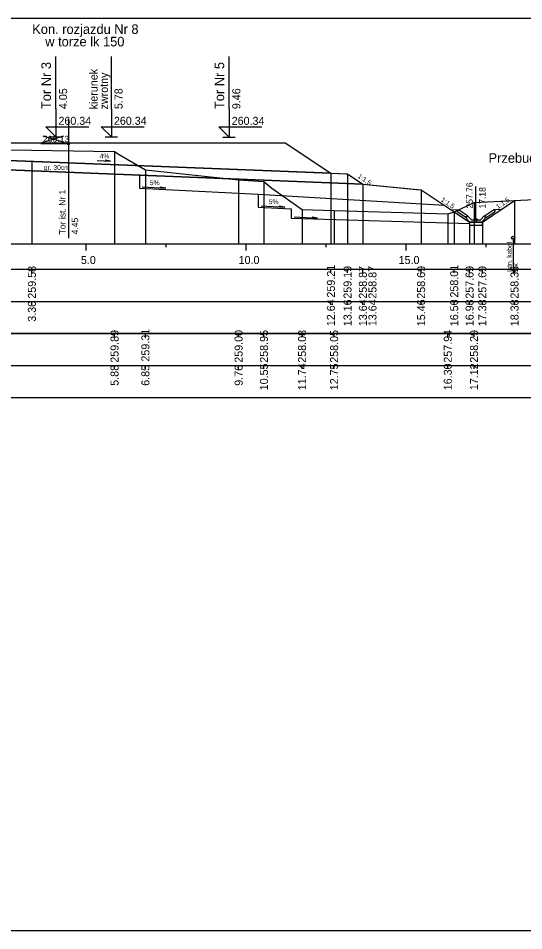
# Model space of a CAD drawing. Extents: x 6516023 to 6560129, y 5513077 to 5529206.
# Drawn here: x 6516681.09 to 6516696.88, y 5514451.16 to 5514479.66 of the extents above; entities that cross this region are included whole.
import ezdxf

# ---------------------------------------------------------------- set-up
doc = ezdxf.new("R2010")
doc.units = 0
for name, color, linetype in [('IR_default', 7, 'Continuous'), ('TOR_PRZEK_P-inne branze', 7, 'Continuous'), ('TOR_PRZEK_P-kable', 7, 'Continuous'), ('TOR_PRZEK_P-komponent', 7, 'Continuous'), ('TOR_PRZEK_P-odwodnienie', 7, 'Continuous'), ('TOR_PRZEK_P-opisy', 7, 'Continuous'), ('TOR_PRZEK_P-schodkowanie+wymiana', 7, 'Continuous'), ('TOR_PRZEK_P-tabelka istniejace', 7, 'Continuous'), ('TOR_PRZEK_P-tabelka projektowane', 7, 'Continuous'), ('TOR_PRZEK_P-teren istniejacy', 7, 'Continuous'), ('TOR_PRZEK_P-tory istniejace', 7, 'Continuous'), ('TOR_PRZEK_P-tory projektowane', 7, 'Continuous'), ('TOR_PRZEK_P-uklad odniesienia', 7, 'Continuous'), ('TOR_PRZEK_P-warstwa ochronna I', 7, 'Continuous'), ('TOR_PRZEK_P-warstwa ochronna II', 7, 'Continuous'), ('TOR_PS_T-skarpy projektowane', 7, 'Continuous'), ('TOR_RAMKI-ramka+tabelka 1', 7, 'Continuous')]:
    doc.layers.add(name, color=color, linetype=linetype)

msp = doc.modelspace()

# ---------------------------------------------------------------- linework, layer by layer
at = {"layer": 'IR_default'}
msp.add_lwpolyline([(6516680.667, 5514475.768), (6516682.263, 5514475.768), (6516682.417, 5514475.768), (6516684.013, 5514475.768), (6516685.751, 5514475.767), (6516685.927, 5514475.767), (6516689.119, 5514475.767), (6516689.427, 5514475.767), (6516690.731, 5514474.898), (6516690.857, 5514474.814), (6516691.332, 5514474.795), (6516691.377, 5514474.793), (6516691.856, 5514474.474), (6516691.856, 5514474.474), (6516693.531, 5514474.307), (6516693.677, 5514474.301), (6516694.62, 5514473.672), (6516694.71, 5514473.612), (6516695.148, 5514473.32), (6516695.19, 5514473.292), (6516695.555, 5514473.292), (6516695.59, 5514473.292), (6516696.274, 5514473.748), (6516696.595, 5514473.962)], dxfattribs=at)
at = {"layer": 'TOR_PRZEK_P-kable'}
msp.add_line((6516696.554, 5514472.803), (6516696.554, 5514471.693), dxfattribs=at)
msp.add_circle((6516696.554, 5514472.803), 0.05, dxfattribs=at)
at = {"layer": 'TOR_PRZEK_P-komponent'}
for points in [[(6516671.963, 5514475.767), (6516673.713, 5514475.767), (6516672.659, 5514475.767), (6516675.463, 5514475.767), (6516676.463, 5514475.767), (6516678.213, 5514475.767), (6516679.963, 5514475.767), (6516680.513, 5514475.768), (6516682.263, 5514475.768), (6516684.013, 5514475.768), (6516685.927, 5514475.767), (6516689.427, 5514475.767), (6516690.857, 5514474.814), (6516680.238, 5514475.238), (6516670.591, 5514474.852)], [(6516670.013, 5514474.829), (6516680.238, 5514475.238), (6516691.377, 5514474.793), (6516691.856, 5514474.474), (6516680.238, 5514474.938), (6516669.534, 5514474.51)]]:
    msp.add_lwpolyline(points, close=True, dxfattribs=at)
at = {"layer": 'TOR_PRZEK_P-odwodnienie'}
for p, q in [((6516695.39, 5514473.362), (6516695.39, 5514474.406)), ((6516695.081, 5514473.421), (6516694.82, 5514473.595)), ((6516695.126, 5514473.487), (6516694.845, 5514473.674)), ((6516695.655, 5514473.487), (6516695.935, 5514473.674)), ((6516695.699, 5514473.421), (6516695.961, 5514473.595)), ((6516695.093, 5514473.437), (6516695.081, 5514473.421)), ((6516695.083, 5514473.457), (6516695.13, 5514473.481)), ((6516695.126, 5514473.487), (6516695.117, 5514473.475)), ((6516695.25, 5514473.362), (6516695.13, 5514473.481)), ((6516695.2, 5514473.292), (6516695.58, 5514473.292)), ((6516695.25, 5514473.362), (6516695.53, 5514473.362)), ((6516695.53, 5514473.362), (6516695.65, 5514473.481)), ((6516695.65, 5514473.481), (6516695.698, 5514473.457)), ((6516695.655, 5514473.487), (6516695.663, 5514473.475)), ((6516695.688, 5514473.437), (6516695.699, 5514473.421))]:
    msp.add_line(p, q, dxfattribs=at)
for points in [[(6516694.599, 5514473.686), (6516694.845, 5514473.674)], [(6516694.795, 5514473.648), (6516694.845, 5514473.674)], [(6516694.795, 5514473.648), (6516694.82, 5514473.595)], [(6516696.182, 5514473.686), (6516695.935, 5514473.674)], [(6516695.986, 5514473.648), (6516695.935, 5514473.674)], [(6516695.986, 5514473.648), (6516695.961, 5514473.595)], [(6516695.117, 5514473.475), (6516695.082, 5514473.456)], [(6516695.082, 5514473.456), (6516695.093, 5514473.437)], [(6516695.13, 5514473.362), (6516695.083, 5514473.457)], [(6516695.2, 5514473.292), (6516695.13, 5514473.362)], [(6516695.19, 5514473.292), (6516695.19, 5514473.292), (6516695.19, 5514473.292), (6516695.19, 5514473.291), (6516695.19, 5514473.292), (6516695.191, 5514473.291), (6516695.19, 5514473.292), (6516695.191, 5514473.292)], [(6516695.59, 5514473.292), (6516695.19, 5514473.292), (6516695.19, 5514473.192), (6516695.59, 5514473.192), (6516695.59, 5514473.292)], [(6516695.58, 5514473.292), (6516695.65, 5514473.362)], [(6516695.59, 5514473.292), (6516695.59, 5514473.292), (6516695.59, 5514473.292), (6516695.59, 5514473.291), (6516695.59, 5514473.292), (6516695.591, 5514473.291), (6516695.59, 5514473.292), (6516695.591, 5514473.292)], [(6516695.65, 5514473.362), (6516695.698, 5514473.457)], [(6516695.663, 5514473.475), (6516695.699, 5514473.456)], [(6516695.699, 5514473.456), (6516695.688, 5514473.437)]]:
    msp.add_lwpolyline(points, dxfattribs=at)
msp.add_circle((6516695.39, 5514473.362), 0.035, dxfattribs=at)
at = {"layer": 'TOR_PRZEK_P-opisy'}
msp.add_lwpolyline([(6516683.552, 5514475.211), (6516683.97, 5514475.192), (6516683.802, 5514475.22)], dxfattribs=at)
at = {"layer": 'TOR_PRZEK_P-schodkowanie+wymiana'}
for p, q in [((6516684.871, 5514474.753), (6516684.871, 5514474.347)), ((6516684.871, 5514474.347), (6516688.588, 5514474.161)), ((6516688.588, 5514474.161), (6516688.588, 5514473.755)), ((6516688.588, 5514474.161), (6516694.403, 5514473.816)), ((6516688.588, 5514473.755), (6516689.611, 5514473.704)), ((6516689.611, 5514473.704), (6516689.611, 5514473.412)), ((6516689.611, 5514473.412), (6516695.19, 5514473.242))]:
    msp.add_line(p, q, dxfattribs=at)
at = {"layer": 'TOR_PRZEK_P-tabelka istniejace'}
for p, q in [((6516684.096, 5514469.706), (6516684.096, 5514469.806)), ((6516685.06, 5514469.706), (6516685.06, 5514469.806)), ((6516687.973, 5514469.706), (6516687.973, 5514469.806)), ((6516688.765, 5514469.706), (6516688.765, 5514469.806)), ((6516689.956, 5514469.706), (6516689.956, 5514469.806)), ((6516690.958, 5514469.706), (6516690.958, 5514469.806)), ((6516694.509, 5514469.706), (6516694.509, 5514469.806)), ((6516695.33, 5514469.706), (6516695.33, 5514469.806)), ((6516637.163, 5514468.806), (6516720.963, 5514468.806)), ((6516684.096, 5514468.706), (6516684.096, 5514468.806)), ((6516685.06, 5514468.706), (6516685.06, 5514468.806)), ((6516687.973, 5514468.706), (6516687.973, 5514468.806)), ((6516688.765, 5514468.706), (6516688.765, 5514468.806)), ((6516689.956, 5514468.706), (6516689.956, 5514468.806)), ((6516690.958, 5514468.706), (6516690.958, 5514468.806)), ((6516694.509, 5514468.706), (6516694.509, 5514468.806)), ((6516695.33, 5514468.706), (6516695.33, 5514468.806))]:
    msp.add_line(p, q, dxfattribs=at)
for points in [[(6516684.096, 5514475.498), (6516684.096, 5514472.806), (6516684.096, 5514472.676), (6516684.096, 5514472.606)], [(6516685.06, 5514474.92), (6516685.06, 5514472.806), (6516685.06, 5514472.676), (6516685.06, 5514472.606)], [(6516687.973, 5514474.606), (6516687.973, 5514472.806), (6516687.973, 5514472.676), (6516687.973, 5514472.606)], [(6516688.765, 5514474.561), (6516688.765, 5514472.806), (6516688.765, 5514472.676), (6516688.765, 5514472.606)], [(6516695.33, 5514473.898), (6516695.33, 5514472.806), (6516695.33, 5514472.676), (6516695.33, 5514472.606)], [(6516689.956, 5514473.684), (6516689.956, 5514472.806), (6516689.956, 5514472.676), (6516689.956, 5514472.606)], [(6516690.958, 5514473.653), (6516690.958, 5514472.806), (6516690.958, 5514472.676), (6516690.958, 5514472.606)], [(6516694.509, 5514473.548), (6516694.509, 5514472.806), (6516694.509, 5514472.676), (6516694.509, 5514472.606)]]:
    msp.add_lwpolyline(points, dxfattribs=at)
msp.add_lwpolyline([(6516637.163, 5514469.806), (6516637.163, 5514467.806), (6516720.963, 5514467.806), (6516720.963, 5514469.806)], close=True, dxfattribs=at)
at = {"layer": 'TOR_PRZEK_P-tabelka projektowane'}
for p, q in [((6516681.513, 5514471.706), (6516681.513, 5514471.806)), ((6516690.857, 5514471.706), (6516690.857, 5514471.806)), ((6516691.377, 5514471.706), (6516691.377, 5514471.806)), ((6516691.856, 5514471.706), (6516691.856, 5514471.806)), ((6516693.677, 5514471.706), (6516693.677, 5514471.806)), ((6516694.71, 5514471.706), (6516694.71, 5514471.806)), ((6516695.19, 5514471.706), (6516695.19, 5514471.806)), ((6516695.59, 5514471.706), (6516695.59, 5514471.806)), ((6516696.595, 5514471.706), (6516696.595, 5514471.806)), ((6516637.163, 5514470.806), (6516720.963, 5514470.806)), ((6516681.513, 5514470.706), (6516681.513, 5514470.806)), ((6516690.857, 5514470.706), (6516690.857, 5514470.806)), ((6516691.377, 5514470.706), (6516691.377, 5514470.806)), ((6516691.856, 5514470.706), (6516691.856, 5514470.806)), ((6516693.677, 5514470.706), (6516693.677, 5514470.806)), ((6516694.71, 5514470.706), (6516694.71, 5514470.806)), ((6516695.19, 5514470.706), (6516695.19, 5514470.806)), ((6516695.59, 5514470.706), (6516695.59, 5514470.806)), ((6516696.595, 5514470.706), (6516696.595, 5514470.806))]:
    msp.add_line(p, q, dxfattribs=at)
for points in [[(6516681.513, 5514475.188), (6516681.513, 5514472.806), (6516681.513, 5514472.676), (6516681.513, 5514472.606)], [(6516690.857, 5514474.814), (6516690.857, 5514472.806), (6516690.857, 5514472.676), (6516690.857, 5514472.606)], [(6516691.377, 5514474.793), (6516691.377, 5514472.806), (6516691.377, 5514472.676), (6516691.377, 5514472.606)], [(6516691.856, 5514474.474), (6516691.856, 5514472.806), (6516691.856, 5514472.676), (6516691.856, 5514472.606)], [(6516693.677, 5514474.301), (6516693.677, 5514472.806), (6516693.677, 5514472.676), (6516693.677, 5514472.606)], [(6516696.595, 5514473.962), (6516696.595, 5514472.806), (6516696.595, 5514472.676), (6516696.595, 5514472.606)], [(6516694.71, 5514473.612), (6516694.71, 5514472.806), (6516694.71, 5514472.676), (6516694.71, 5514472.606)], [(6516695.19, 5514473.292), (6516695.19, 5514472.806), (6516695.19, 5514472.676), (6516695.19, 5514472.606)], [(6516695.59, 5514473.292), (6516695.59, 5514472.806), (6516695.59, 5514472.676), (6516695.59, 5514472.606)]]:
    msp.add_lwpolyline(points, dxfattribs=at)
msp.add_lwpolyline([(6516637.163, 5514471.806), (6516637.163, 5514469.806), (6516720.963, 5514469.806), (6516720.963, 5514471.806)], close=True, dxfattribs=at)
at = {"layer": 'TOR_PRZEK_P-teren istniejacy'}
msp.add_lwpolyline([(6516666.573, 5514475.104), (6516667.46, 5514475.506), (6516668.217, 5514475.533), (6516670.569, 5514475.616), (6516670.766, 5514475.522), (6516671.519, 5514475.169), (6516672.091, 5514475.169), (6516672.2, 5514475.171), (6516672.388, 5514475.284), (6516673.11, 5514475.685), (6516675.652, 5514475.631), (6516684.096, 5514475.498), (6516684.242, 5514475.398), (6516685.06, 5514474.92), (6516687.973, 5514474.606), (6516688.765, 5514474.561), (6516689.013, 5514474.344), (6516689.956, 5514473.684), (6516690.958, 5514473.653), (6516694.509, 5514473.548), (6516694.72, 5514473.61), (6516695.33, 5514473.898), (6516698.471, 5514474.057)], dxfattribs=at)
at = {"layer": 'TOR_PRZEK_P-tory istniejace'}
for p, q in [((6516682.658, 5514476.512), (6516682.658, 5514472.791)), ((6516681.858, 5514475.783), (6516682.51, 5514475.986)), ((6516681.858, 5514475.986), (6516682.51, 5514475.783)), ((6516682.658, 5514475.736), (6516681.792, 5514475.736))]:
    msp.add_line(p, q, dxfattribs=at)
msp.add_circle((6516682.658, 5514475.736), 0.035, dxfattribs=at)
at = {"layer": 'TOR_PRZEK_P-tory projektowane'}
for p, q in [((6516682.263, 5514476.826), (6516682.263, 5514478.458)), ((6516683.996, 5514476.826), (6516683.996, 5514478.458)), ((6516687.677, 5514476.825), (6516687.677, 5514478.457)), ((6516682.263, 5514476.826), (6516682.263, 5514475.948)), ((6516683.996, 5514476.826), (6516683.996, 5514475.948)), ((6516687.677, 5514476.825), (6516687.677, 5514475.947)), ((6516682.263, 5514475.948), (6516681.944, 5514476.267)), ((6516681.944, 5514476.267), (6516683.288, 5514476.267)), ((6516683.996, 5514475.948), (6516683.677, 5514476.267)), ((6516683.677, 5514476.267), (6516685.021, 5514476.267)), ((6516687.677, 5514475.947), (6516687.358, 5514476.266)), ((6516687.358, 5514476.266), (6516688.702, 5514476.266)), ((6516682.071, 5514475.948), (6516682.455, 5514475.948)), ((6516683.805, 5514475.948), (6516684.188, 5514475.948)), ((6516687.485, 5514475.947), (6516687.869, 5514475.947))]:
    msp.add_line(p, q, dxfattribs=at)
at = {"layer": 'TOR_PRZEK_P-uklad odniesienia'}
for p, q in [((6516640.963, 5514472.606), (6516720.963, 5514472.606)), ((6516683.213, 5514472.406), (6516683.213, 5514472.606)), ((6516685.713, 5514472.506), (6516685.713, 5514472.606)), ((6516688.213, 5514472.406), (6516688.213, 5514472.606)), ((6516690.713, 5514472.506), (6516690.713, 5514472.606)), ((6516693.213, 5514472.406), (6516693.213, 5514472.606)), ((6516695.713, 5514472.506), (6516695.713, 5514472.606))]:
    msp.add_line(p, q, dxfattribs=at)
at = {"layer": 'TOR_PRZEK_P-warstwa ochronna I'}
msp.add_lwpolyline([(6516669.534, 5514474.51), (6516680.238, 5514474.938), (6516691.856, 5514474.474)], dxfattribs=at)
at = {"layer": 'TOR_PRZEK_P-warstwa ochronna II'}
msp.add_lwpolyline([(6516659.779, 5514474.338), (6516660.886, 5514474.36), (6516662.236, 5514473.459), (6516662.636, 5514473.459), (6516663.041, 5514473.729), (6516663.713, 5514474.177), (6516669.534, 5514474.51), (6516670.013, 5514474.829), (6516670.591, 5514474.852), (6516678.963, 5514475.187), (6516680.238, 5514475.238), (6516681.513, 5514475.188), (6516690.857, 5514474.814), (6516691.377, 5514474.793), (6516691.856, 5514474.474), (6516693.677, 5514474.301), (6516694.71, 5514473.612), (6516695.19, 5514473.292), (6516695.59, 5514473.292), (6516696.595, 5514473.962)], dxfattribs=at)
at = {"layer": 'TOR_PS_T-skarpy projektowane'}
for points in [[(6516684.964, 5514474.391), (6516685.699, 5514474.352), (6516685.526, 5514474.382)], [(6516688.681, 5514473.799), (6516689.416, 5514473.76), (6516689.244, 5514473.791)], [(6516689.704, 5514473.457), (6516690.439, 5514473.417), (6516690.267, 5514473.448)]]:
    msp.add_lwpolyline(points, dxfattribs=at)
at = {"layer": 'TOR_RAMKI-ramka+tabelka 1'}
msp.add_lwpolyline([(6516634.513, 5514479.656), (6516882.013, 5514479.656), (6516882.013, 5514451.156), (6516634.513, 5514451.156)], close=True, dxfattribs=at)

# ---------------------------------------------------------------- texts
at = {"layer": 'TOR_PRZEK_P-inne branze'}
msp.add_text('Przebudowa i budowa układu drogowego', height=0.3, dxfattribs=at).set_placement((6516695.784, 5514475.142))
at = {"layer": 'TOR_PRZEK_P-kable'}
for s, height, p in [('Istn. kabel', 0.14999, (6516696.509, 5514471.729)), ('srk', 0.15, (6516696.703, 5514471.729))]:
    msp.add_text(s, height=height, rotation=90.0511, dxfattribs=at).set_placement(p)
at = {"layer": 'TOR_PRZEK_P-odwodnienie'}
for s, p in [('257.76', (6516695.29, 5514473.712)), ('17.18', (6516695.69, 5514473.712))]:
    msp.add_text(s, height=0.2, rotation=90, dxfattribs=at).set_placement(p)
at = {"layer": 'TOR_PRZEK_P-opisy'}
for s, rotation, p in [('4%', 359.8485, (6516683.631, 5514475.277)), ('1:1,5', 325.9299, (6516691.678, 5514474.688)), ('1:1,5', 325.9299, (6516694.279, 5514473.956)), ('1:1,5', 34.0701, (6516696.079, 5514473.69))]:
    msp.add_text(s, height=0.15, rotation=rotation, dxfattribs=at).set_placement(p)
at = {"layer": 'TOR_PRZEK_P-tabelka istniejace'}
for s, p in [('259.89', (6516684.221, 5514468.898)), ('259.31', (6516685.185, 5514468.933)), ('259.00', (6516688.098, 5514468.898)), ('258.95', (6516688.89, 5514468.897)), ('258.08', (6516690.081, 5514468.898)), ('258.05', (6516691.083, 5514468.897)), ('257.94', (6516694.634, 5514468.899)), ('258.29', (6516695.455, 5514468.898)), ('5.88', (6516684.221, 5514468.177)), ('6.85', (6516685.185, 5514468.177)), ('9.76', (6516688.098, 5514468.177)), ('10.55', (6516688.89, 5514468.037)), ('11.74', (6516690.081, 5514468.039)), ('12.75', (6516691.083, 5514468.037)), ('16.30', (6516694.634, 5514468.038)), ('17.12', (6516695.455, 5514468.04))]:
    msp.add_text(s, height=0.25, rotation=90, dxfattribs=at).set_placement(p)
at = {"layer": 'TOR_PRZEK_P-tabelka projektowane'}
for s, p in [('259.58', (6516681.638, 5514470.898)), ('259.21', (6516690.982, 5514470.933)), ('259.19', (6516691.502, 5514470.898)), ('258.87', (6516691.981, 5514470.898)), ('258.87', (6516692.281, 5514470.898)), ('258.69', (6516693.802, 5514470.898)), ('258.01', (6516694.835, 5514470.933)), ('257.69', (6516695.315, 5514470.898)), ('257.69', (6516695.715, 5514470.898)), ('258.36', (6516696.72, 5514470.898)), ('3.30', (6516681.638, 5514470.178)), ('12.64', (6516690.982, 5514470.039)), ('13.16', (6516691.502, 5514470.038)), ('13.64', (6516691.981, 5514470.039)), ('13.64', (6516692.281, 5514470.039)), ('15.46', (6516693.802, 5514470.038)), ('16.50', (6516694.835, 5514470.038)), ('16.98', (6516695.315, 5514470.038)), ('17.38', (6516695.715, 5514470.038)), ('18.38', (6516696.72, 5514470.038))]:
    msp.add_text(s, height=0.25, rotation=90, dxfattribs=at).set_placement(p)
at = {"layer": 'TOR_PRZEK_P-tory istniejace'}
msp.add_text('260.13', height=0.2, dxfattribs=at).set_placement((6516681.858, 5514475.786))
for s, rotation, p in [('Tor ist. Nr 1', 90.0511, (6516682.564, 5514472.906)), ('4.45', 90, (6516682.958, 5514472.906))]:
    msp.add_text(s, height=0.2, rotation=rotation, dxfattribs=at).set_placement(p)
at = {"layer": 'TOR_PRZEK_P-tory projektowane'}
for s, height, rotation, p in [('Kon. rozjazdu Nr 8', 0.3, 360, (6516681.524, 5514479.166)), ('w torze lk 150', 0.3, 360, (6516681.93, 5514478.777)), ('Tor Nr 3', 0.3, 90, (6516682.108, 5514476.819)), ('Tor Nr 5', 0.3, 90, (6516687.522, 5514476.819)), ('kierunek', 0.25, 90, (6516683.566, 5514476.809)), ('zwrotny', 0.25, 90, (6516683.89, 5514476.809)), ('4.05', 0.25, 90, (6516682.613, 5514476.818)), ('5.78', 0.25, 90, (6516684.346, 5514476.818)), ('9.46', 0.25, 90, (6516688.027, 5514476.817))]:
    msp.add_text(s, height=height, rotation=rotation, dxfattribs=at).set_placement(p)
for p in [(6516682.343, 5514476.328), (6516684.076, 5514476.328), (6516687.757, 5514476.327)]:
    msp.add_text('260.34', height=0.25, dxfattribs=at).set_placement(p)
at = {"layer": 'TOR_PRZEK_P-uklad odniesienia'}
for s, p in [('5.0', (6516683.044, 5514471.981)), ('10.0', (6516687.974, 5514471.981)), ('15.0', (6516692.974, 5514471.981))]:
    msp.add_text(s, height=0.25, dxfattribs=at).set_placement(p)
at = {"layer": 'TOR_PRZEK_P-warstwa ochronna I'}
msp.add_text('gr. 30cm', height=0.15, dxfattribs=at).set_placement((6516681.887, 5514474.92))
at = {"layer": 'TOR_PS_T-skarpy projektowane'}
for p in [(6516685.196, 5514474.443), (6516688.913, 5514473.851)]:
    msp.add_text('5%', height=0.1545, dxfattribs=at).set_placement(p)

doc.saveas('drawing.dxf')
